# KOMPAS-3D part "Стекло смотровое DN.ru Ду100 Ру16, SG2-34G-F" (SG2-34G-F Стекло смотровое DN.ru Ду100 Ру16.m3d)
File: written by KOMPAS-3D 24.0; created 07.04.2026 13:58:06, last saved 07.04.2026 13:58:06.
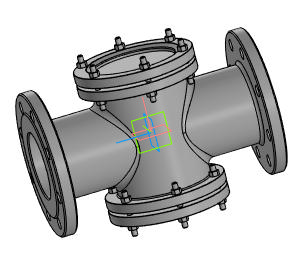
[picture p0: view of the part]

Document properties: Автор: Main; Полное имя файла: D:\DN.ru Аутсерс\Стекло смотровое DN.ru\Исходники\Стекло смотровое DN.ru SG2-34G-F тип В ГОСТ 21836-2021 Ду100 Ру16, углеродистая сталь, фланцевое\SG2-34G-F Стекло смотровое DN.ru Ду100 Ру16.m3d

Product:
- Part/product: Стекло смотровое DN.ru Ду100 Ру16  | designation SG2-34G-F
    Масса: 26
    Раздел спецификации: Прочие изделия
    Примечание: D500-00087

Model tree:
1. Операция без истории:1

Expressions: SG2-34G-F
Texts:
  Точка начала. Х
  Точка начала. Y
  Точка начала. Z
